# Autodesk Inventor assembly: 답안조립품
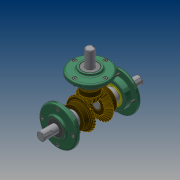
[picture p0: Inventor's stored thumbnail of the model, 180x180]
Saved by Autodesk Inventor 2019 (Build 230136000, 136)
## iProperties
Created: 2019-03
Part Number: 답안조립품
Material: 일반
Document SubType Name: Assembly
Designer: PC312-10
Author: PC312-10
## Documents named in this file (16)
- C:\Users\PC312-10\Desktop\490314V1010\답안조립품.iam
- C:\Users\PC312-10\Desktop\490314V1010\본체.ipt
- C:\Users\PC312-10\Desktop\490314V1010\커버.ipt
- C:\Users\PC312-10\Desktop\490314V1010\베어링 6203.ipt
- C:\Users\PC312-10\Desktop\490314V1010\오일 실.ipt
- 오일 실.ipt
- C:\Users\PC312-10\Desktop\490314V1010\메인 축.ipt
- 메인 축.ipt
- C:\Users\PC312-10\Desktop\490314V1010\키 5x5.ipt
- C:\Users\PC312-10\Desktop\490314V1010\서브 축.ipt
- 서브 축.ipt
- C:\Users\PC312-10\Desktop\490314V1010\키 4x4.ipt
- C:\Users\PC312-10\Desktop\490314V1010\볼트 M4.ipt
- 볼트 M4.ipt
- C:\Users\PC312-10\Desktop\490314V1010\메인 베벨기어.ipt
- C:\Users\PC312-10\Desktop\490314V1010\서브 베벨기어.ipt
